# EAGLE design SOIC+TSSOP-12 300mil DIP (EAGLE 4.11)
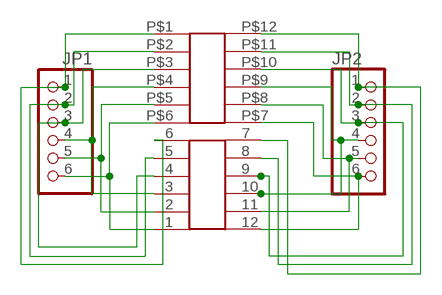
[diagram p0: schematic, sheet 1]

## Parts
JP1  PINHD-1X6  [1X06]
JP2  PINHD-1X6  [1X06]
U$1  SMD-12SOIC  [SO-12NMW]
U$2  SMD-12TSSOP  [TSSOP-12NM]

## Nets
N$1: JP1.1 U$1.P$1 U$2.6
N$3: JP1.2 U$1.P$2 U$2.5
N$4: JP1.5 U$1.P$5 U$2.2
N$5: JP1.4 U$1.P$4 U$2.3
N$6: JP1.3 U$1.P$3 U$2.4
N$7: JP1.6 U$1.P$6 U$2.1
N$9: JP2.1 U$1.P$12 U$2.7
N$10: JP2.2 U$1.P$11 U$2.8
N$12: JP2.3 U$1.P$10 U$2.9
N$13: JP2.5 U$1.P$8 U$2.11
N$14: JP2.6 U$1.P$7 U$2.12
N$16: JP2.4 U$1.P$9 U$2.10

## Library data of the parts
JP1 JP2 = pinhead:PINHD-1X6: PIN HEADER
U$1 U$2 = boogie:SMD-12

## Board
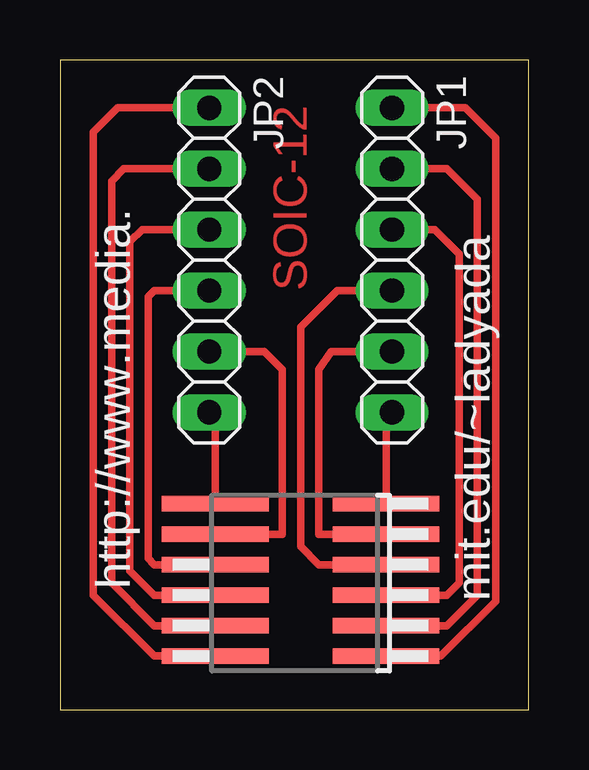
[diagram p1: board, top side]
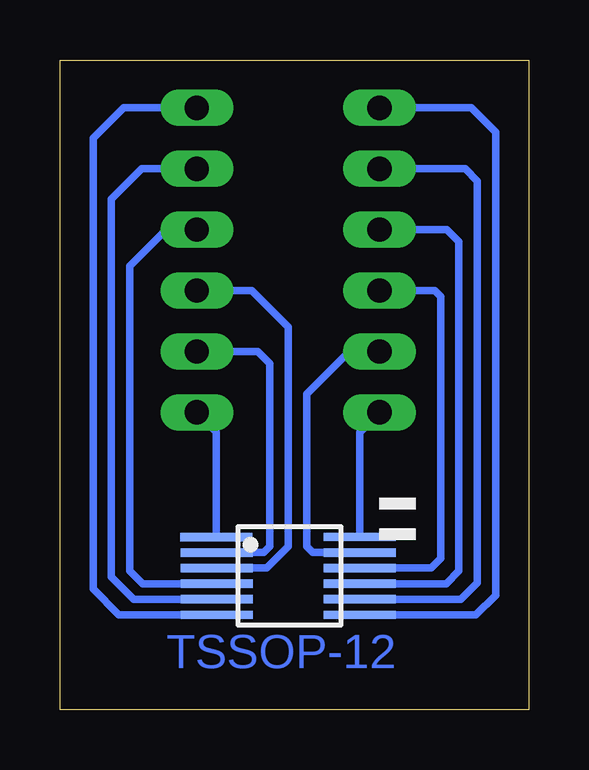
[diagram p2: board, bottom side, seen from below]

Size 19.54 x 27.1 mm. Coordinates in mm from the lower left corner, seen from the top.
Outline: 0,0 19.54,0 19.54,27.1 0,27.1 0,0
Copper layers (1*16): Top 0.035mm / dielectric 1.5mm / Bottom 0.035mm
Design rules "default": minimum track width 10mil, minimum drill 24mil, track to track 8mil, track to pad 8mil, pad to pad 8mil, via to via 8mil, smd to smd 8mil, copper to edge 40mil, drill to drill 8mil, minimum pad ring 10mil, minimum via ring 8mil, stop-mask expansion 4mil, vias tented up to drill 0mil, thermal gap 10mil

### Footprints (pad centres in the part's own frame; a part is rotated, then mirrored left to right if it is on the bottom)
1X06 = drill 1.016 long: 1 -6.35,0; 2 -3.81,0; 3 -1.27,0; 4 1.27,0; 5 3.81,0; 6 6.35,0
SO-12NMW = smd 0.635 x 4.445: P$1 -2.54,-4.826; P$2 -1.27,-4.826; P$3 0,-4.826; P$4 1.27,-4.826; P$5 2.54,-4.826; P$6 3.81,-4.826; P$7 3.81,2.286; P$8 2.54,2.286; P$9 1.27,2.286; P$10 0,2.286; P$11 -1.27,2.286; P$12 -2.54,2.286
TSSOP-12NM = smd 0.35 x 3: 1 -0.895,-2.993; 2 -0.255,-2.969; 3 0.395,-2.969; 4 1.045,-2.969; 5 1.695,-2.969; 6 2.345,-2.969; 7 2.345,2.981; 8 1.695,2.981; 9 1.045,2.981; 10 0.395,2.981; 11 -0.255,2.981; 12 -0.905,2.981

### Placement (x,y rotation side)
JP1  13.84,18.76 270 top
JP2  6.22,18.76 270 top
U$1  8.76,4.79 90 top
U$2  10.03,6.31 270 bottom

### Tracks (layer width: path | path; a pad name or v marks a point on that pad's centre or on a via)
N$1
  Top 0.305: U$1.P$1 15.87,2.25 18.16,4.53 18.16,23.84 16.89,25.11 JP1.1
  Bottom 0.305: U$2.6 17.08,3.97 18.16,5.04 18.16,23.84 16.89,25.11 JP1.1
N$3
  Top 0.305: U$1.P$2 16.12,3.52 17.39,4.79 17.39,21.3 16.12,22.57 JP1.2
  Bottom 0.305: U$2.5 16.46,4.62 17.39,5.55 17.39,21.3 16.12,22.57 JP1.2
N$4
  Top 0.305: U$1.P$5 10.79,7.33 10.79,14.19 11.3,14.95 JP1.5
  Bottom 0.305: U$2.2 11.04,6.57 10.79,6.82 10.79,14.44 11.3,14.95 JP1.5
N$5
  Top 0.305: U$1.P$4 10.79,6.06 10.03,6.82 10.03,15.96 11.55,17.49 JP1.4
  Bottom 0.305: U$2.3 10.93,5.92 10.03,6.82 10.03,15.96 11.55,17.49 JP1.4
N$6
  Top 0.305: U$1.P$3 16.12,4.79 16.63,5.3 16.63,19.01 15.62,20.03 JP1.3
  Bottom 0.305: U$2.4 16.09,5.27 16.63,5.8 16.63,18.5 15.11,20.03 JP1.3
N$7
  Top 0.305: JP1.6 14.09,12.41 13.58,11.9 U$1.P$6
  Bottom 0.305: U$2.1 13.02,11.59 JP1.6
N$9
  Top 0.305: U$1.P$12 3.93,2.25 1.39,4.79 1.39,24.09 2.41,25.11 JP2.1
  Bottom 0.305: U$2.7 2.21,3.97 1.39,4.79 1.39,24.09 2.41,25.11 JP2.1 6.47,25.11
N$10
  Top 0.305: U$1.P$11 3.93,3.52 2.15,5.3 2.15,22.06 2.66,22.57 JP2.2 5.96,22.57
  Bottom 0.305: U$2.8 2.83,4.62 2.15,5.3 2.15,22.06 2.66,22.57 5.96,22.57 6.22,22.82 JP2.2
N$12
  Top 0.305: U$1.P$10 3.93,4.79 2.92,5.8 2.92,19.52 3.42,20.03 JP2.3
  Bottom 0.305: U$2.9 3.45,5.27 2.92,5.8 2.92,19.52 3.42,20.03 JP2.3
N$13
  Top 0.305: U$1.P$8 9.27,7.33 9.27,14.19 8.5,14.95 JP2.5
  Bottom 0.305: U$2.11 9.01,6.57 9.27,6.82 9.27,13.17 7.49,14.95 JP2.5
N$14
  Top 0.305: U$1.P$7 6.47,11.65 JP2.6
  Bottom 0.305: U$2.12 7.05,11.58 JP2.6
N$16
  Top 0.305: U$1.P$9 3.93,6.06 3.68,6.31 3.68,17.23 3.93,17.49 JP2.4 5.96,17.49
  Bottom 0.305: U$2.10 4.07,5.92 3.68,6.31 3.68,17.23 3.93,17.49 5.96,17.49 6.22,17.74 JP2.4

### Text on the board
Top: SOIC-12
Bottom: TSSOP-12
tPlace: http://www.media. | mit.edu/~ladyada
